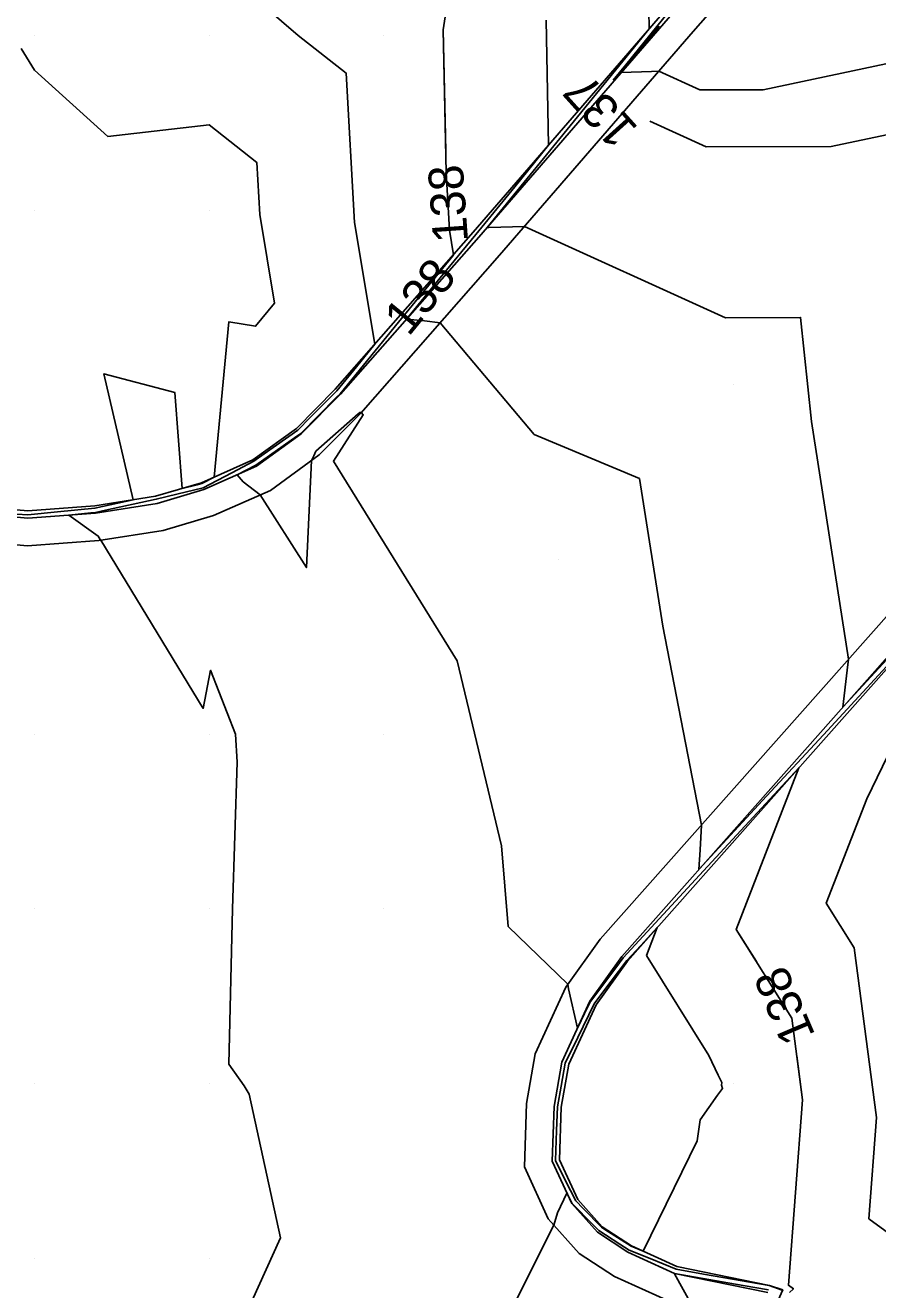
# Model space of a CAD drawing. Extents: x 2354170 to 2357230, y 866100 to 868290.
# Drawn here: x 2354819.4 to 2354868.2, y 867508.2 to 867580.6 of the extents above; entities that cross this region are included whole.
import ezdxf

# ---------------------------------------------------------------- set-up
doc = ezdxf.new("R2010")
doc.units = 0
for name, color, linetype in [('Default', 7, 'Continuous'), ('DTM Contours Minor', 7, 'Continuous'), ('DTM Contours Minor Text', 7, 'Continuous'), ('Exist DTM QL2 LIDAR Elevation Point', 7, 'Continuous'), ('PH Exist DTM Breakline', 7, 'Continuous')]:
    doc.layers.add(name, color=color, linetype=linetype)

msp = doc.modelspace()

# ---------------------------------------------------------------- linework, layer by layer
at = {"layer": 'Default'}
for points in [[(2354815.726, 867595.775), (2354819.969, 867593.647), (2354822.943, 867592.992), (2354829.969, 867593.427), (2354833.225, 867593.273), (2354835.838, 867590.017), (2354837.717, 867587.765), (2354839.969, 867585.813), (2354843.919, 867583.967), (2354843.368, 867580.339), (2354843.539, 867572.167), (2354843.729, 867568.862), (2354843.963, 867567.463), (2354843.933, 867567.427)], [(2354832.338, 867582.386), (2354835.07, 867580.017), (2354837.809, 867577.857), (2354838.3, 867569.318), (2354839.465, 867562.354), (2354838.403, 867561.055), (2354837.281, 867559.682), (2354835.759, 867558.14), (2354835.054, 867557.425), (2354833.116, 867556.063), (2354832.523, 867555.646), (2354831.27, 867554.988), (2354829.636, 867554.127), (2354828.119, 867553.756), (2354826.941, 867553.469), (2354824.04, 867552.835), (2354823.463, 867552.709), (2354823.2, 867552.683), (2354821.949, 867552.561), (2354823.62, 867551.358), (2354823.742, 867551.158), (2354823.772, 867551.119), (2354829.637, 867541.493), (2354830.043, 867543.68), (2354831.48, 867540.017), (2354831.575, 867538.411), (2354831.312, 867530.017), (2354831.096, 867521.144), (2354831.971, 867519.891), (2354832.27, 867519.41), (2354834.05, 867511.201), (2354832.414, 867507.572)], [(2354849.257, 867580.897), (2354849.407, 867573.73), (2354847.47, 867571.36), (2354845.234, 867568.625), (2354843.204, 867566.14), (2354841.273, 867563.777), (2354842.298, 867563.678), (2354843.201, 867563.572), (2354848.584, 867557.178), (2354854.606, 867554.654), (2354855.937, 867546.198), (2354858.153, 867534.821), (2354858.085, 867533.411), (2354858.01, 867532.276), (2354861.885, 867536.465), (2354865.135, 867539.979), (2354872.56, 867548.041)], [(2354855.146, 867581.455), (2354855.169, 867580.386), (2354850.645, 867574.85), (2354845.879, 867569.019), (2354845.98, 867569.022), (2354848.033, 867569.087), (2354859.536, 867563.86), (2354863.83, 867563.878), (2354864.452, 867557.911), (2354866.573, 867544.307), (2354866.5, 867543.68), (2354866.258, 867541.567), (2354875.841, 867551.974)], [(2354856.333, 867581.417), (2354853.82, 867578.341), (2354853.092, 867577.45)], [(2354819.217, 867579.265), (2354819.969, 867578.022), (2354824.179, 867574.227), (2354829.969, 867574.902), (2354832.7, 867572.748), (2354832.871, 867569.774), (2354833.721, 867564.691), (2354832.628, 867563.372), (2354831.093, 867563.621), (2354830.265, 867554.739), (2354829.549, 867554.362), (2354829.277, 867554.296), (2354828.431, 867554.09), (2354828.014, 867559.576), (2354823.938, 867560.641), (2354825.629, 867553.438), (2354823.435, 867552.957), (2354821.283, 867552.747), (2354819.587, 867552.582), (2354818.33, 867552.662)], [(2354855.209, 867575.102), (2354858.432, 867573.638), (2354865.584, 867573.667), (2354869.828, 867574.56)], [(2354840.136, 867562.781), (2354837.464, 867559.511), (2354837.253, 867559.298), (2354835.218, 867557.235), (2354834.984, 867557.071), (2354832.649, 867555.428), (2354831.568, 867554.86), (2354831.918, 867554.474), (2354832.89, 867553.714), (2354835.538, 867549.556), (2354835.836, 867555.685), (2354835.974, 867555.949), (2354836.089, 867556.219), (2354838.505, 867558.352), (2354838.608, 867558.442), (2354838.678, 867558.434), (2354838.794, 867558.296), (2354837.083, 867555.65), (2354844.179, 867544.227), (2354846.708, 867533.632), (2354847.088, 867529.021), (2354850.514, 867525.712), (2354850.551, 867525.446), (2354851.054, 867523.197), (2354851.677, 867524.475), (2354851.798, 867524.722), (2354853.253, 867526.658), (2354853.68, 867527.226), (2354858.281, 867532.2), (2354863.74, 867538.103), (2354860.15, 867528.85), (2354861.301, 867527.007)], [(2354869.112, 867539.399), (2354867.614, 867536.317), (2354865.298, 867530.348), (2354866.899, 867527.786), (2354868.181, 867518.091), (2354867.741, 867512.287), (2354872.017, 867509.175)], [(2354855.001, 867527.353), (2354855.626, 867528.962), (2354854.676, 867527.935), (2354853.876, 867527.07), (2354852.513, 867525.258), (2354852.015, 867524.596), (2354851.074, 867522.669), (2354850.355, 867521.195), (2354850.123, 867519.879), (2354849.915, 867518.697), (2354849.861, 867517.346), (2354849.793, 867515.614), (2354850.36, 867514.486), (2354850.958, 867513.304), (2354851.389, 867512.865), (2354852.441, 867511.796), (2354852.63, 867511.675), (2354854.13, 867510.713), (2354854.812, 867510.436), (2354857.911, 867516.738), (2354858.075, 867517.948), (2354859.078, 867519.351), (2354859.362, 867519.75), (2354859.307, 867519.926), (2354859.32, 867520.094), (2354859.119, 867520.506), (2354858.573, 867521.637), (2354855.001, 867527.353)], [(2354863.608, 867521.605), (2354863.942, 867519.085), (2354863.137, 867508.482), (2354863.419, 867508.276), (2354863.2, 867508.059)], [(2354862.776, 867508.207), (2354862.041, 867508.459), (2354858.266, 867509.124), (2354856.699, 867509.4), (2354855.216, 867510.004), (2354854.01, 867510.493), (2354853.477, 867510.835), (2354852.277, 867511.605), (2354851.936, 867511.951), (2354850.747, 867513.165), (2354850.693, 867513.272), (2354850.452, 867513.751), (2354849.924, 867512.626), (2354849.698, 867511.926), (2354846.965, 867506.446)], [(2354861.99, 867508.215), (2354860.546, 867508.469), (2354856.622, 867509.161), (2354856.608, 867509.166), (2354856.609, 867509.16), (2354856.615, 867509.14), (2354857.597, 867507.343)]]:
    msp.add_lwpolyline(points, dxfattribs=at)
at = {"layer": 'DTM Contours Minor'}
for points in [[(2354815.726, 867595.775), (2354819.969, 867593.647), (2354822.943, 867592.992), (2354829.969, 867593.427), (2354833.225, 867593.273), (2354835.838, 867590.017), (2354837.717, 867587.765), (2354839.969, 867585.813), (2354843.919, 867583.967), (2354843.368, 867580.339), (2354843.513, 867573.391)], [(2354855.737, 867580.556), (2354854.878, 867579.504), (2354853.562, 867577.894), (2354855.298, 867577.95), (2354855.717, 867577.963), (2354858.064, 867576.897), (2354861.685, 867576.912), (2354869.702, 867578.598)], [(2354843.933, 867567.427), (2354840.803, 867563.597), (2354837.464, 867559.511), (2354837.253, 867559.298), (2354835.218, 867557.235), (2354834.984, 867557.071), (2354832.649, 867555.428), (2354831.568, 867554.86), (2354831.918, 867554.474), (2354832.89, 867553.714), (2354835.538, 867549.556), (2354835.836, 867555.685), (2354835.974, 867555.949), (2354836.089, 867556.219), (2354838.505, 867558.352), (2354838.608, 867558.442), (2354838.678, 867558.434), (2354838.794, 867558.296), (2354837.083, 867555.65), (2354844.179, 867544.227), (2354846.708, 867533.632), (2354847.088, 867529.021), (2354850.514, 867525.712), (2354850.551, 867525.446), (2354851.054, 867523.197), (2354851.677, 867524.475), (2354851.798, 867524.722), (2354853.253, 867526.658), (2354853.68, 867527.226), (2354858.281, 867532.2), (2354863.74, 867538.103), (2354860.15, 867528.85), (2354863.321, 867523.775), (2354863.942, 867519.085), (2354863.137, 867508.482), (2354863.419, 867508.276), (2354863.2, 867508.059)], [(2354862.776, 867508.207), (2354862.041, 867508.459), (2354858.266, 867509.124), (2354856.699, 867509.4), (2354855.216, 867510.004), (2354854.01, 867510.493), (2354853.477, 867510.835), (2354852.277, 867511.605), (2354851.936, 867511.951), (2354850.747, 867513.165), (2354850.693, 867513.272), (2354850.452, 867513.751), (2354849.924, 867512.626), (2354849.698, 867511.926), (2354846.965, 867506.446)]]:
    msp.add_lwpolyline(points, dxfattribs=at)
at = {"layer": 'Exist DTM QL2 LIDAR Elevation Point'}
for p, q in [((2354819.969, 867580.017), (2354819.969, 867580.017)), ((2354829.969, 867580.017), (2354829.969, 867580.017)), ((2354839.969, 867580.017), (2354839.969, 867580.017)), ((2354819.969, 867570.017), (2354819.969, 867570.017)), ((2354829.969, 867570.017), (2354829.969, 867570.017)), ((2354859.97, 867560.017), (2354859.97, 867560.017)), ((2354849.97, 867550.017), (2354849.97, 867550.017)), ((2354819.969, 867540.017), (2354819.969, 867540.017)), ((2354829.969, 867540.017), (2354829.969, 867540.017)), ((2354839.969, 867540.017), (2354839.969, 867540.017)), ((2354819.969, 867530.017), (2354819.969, 867530.017)), ((2354829.969, 867530.017), (2354829.969, 867530.017)), ((2354839.969, 867530.017), (2354839.969, 867530.017)), ((2354819.969, 867520.017), (2354819.969, 867520.017)), ((2354829.969, 867520.017), (2354829.969, 867520.017)), ((2354859.97, 867520.017), (2354859.97, 867520.017)), ((2354819.969, 867510.017), (2354819.969, 867510.017)), ((2354829.969, 867510.017), (2354829.969, 867510.017))]:
    msp.add_line(p, q, dxfattribs=at)
at = {"layer": 'PH Exist DTM Breakline'}
for points in [[(2354860.36, 867585.697), (2354856.492, 867581.279), (2354845.407, 867568.474), (2354837.493, 867559.484), (2354835.24, 867557.209), (2354832.69, 867555.357), (2354829.674, 867554.022), (2354826.994, 867553.232), (2354823.467, 867552.674), (2354819.586, 867552.386), (2354816.224, 867552.693), (2354813.064, 867554.32)], [(2354859.943, 867585.854), (2354856.178, 867581.552), (2354845.093, 867568.748), (2354837.188, 867559.768), (2354834.968, 867557.526), (2354832.481, 867555.72), (2354829.531, 867554.414), (2354826.902, 867553.639), (2354823.419, 867553.088), (2354819.589, 867552.804), (2354816.343, 867553.101), (2354813.255, 867554.69)], [(2354861.864, 867585.012), (2354857.686, 867580.239), (2354846.6, 867567.432), (2354838.651, 867558.403), (2354836.274, 867556.003), (2354833.485, 867553.977), (2354830.221, 867552.532), (2354827.343, 867551.684), (2354823.65, 867551.1), (2354819.572, 867550.797), (2354815.773, 867551.144), (2354812.34, 867552.912)], [(2354885.483, 867565.392), (2354874.467, 867553.204), (2354863.791, 867541.172), (2354852.351, 867528.285), (2354850.391, 867525.539), (2354848.634, 867521.731), (2354848.139, 867518.879), (2354848.024, 867515.259), (2354849.386, 867512.273), (2354851.159, 867510.301), (2354853.179, 867508.98), (2354856.129, 867507.645), (2354859.691, 867506.913)], [(2354886.658, 867564.33), (2354875.647, 867552.148), (2354864.975, 867540.121), (2354853.591, 867527.297), (2354851.766, 867524.741), (2354850.158, 867521.256), (2354849.718, 867518.718), (2354849.618, 867515.579), (2354850.726, 867513.151), (2354852.198, 867511.513), (2354853.943, 867510.372), (2354856.621, 867509.16), (2354861.959, 867508.063)], [(2354886.967, 867564.051), (2354875.957, 867551.87), (2354865.287, 867539.845), (2354853.917, 867527.037), (2354852.128, 867524.531), (2354850.56, 867521.131), (2354850.133, 867518.675), (2354850.038, 867515.663), (2354851.078, 867513.382), (2354852.472, 867511.832), (2354854.144, 867510.739), (2354856.751, 867509.559), (2354862.043, 867508.471)], [(2354862.043, 867508.471), (2354862.812, 867508.213), (2354861.573, 867505.474)]]:
    msp.add_lwpolyline(points, dxfattribs=at)

# ---------------------------------------------------------------- texts
at = {"layer": 'Default'}
for s, rotation, p in [('137', 132.02909, (2354854.594, 867574.701)), ('138', 50.74326, (2354841.389, 867562.733)), ('138', 113.12291, (2354864.692, 867522.792))]:
    msp.add_text(s, height=2, rotation=rotation, dxfattribs=at).set_placement(p)
at = {"layer": 'DTM Contours Minor Text'}
msp.add_text('138', height=2, rotation=94.02479, dxfattribs=at).set_placement((2354844.796, 867568.226))

doc.saveas('drawing.dxf')
